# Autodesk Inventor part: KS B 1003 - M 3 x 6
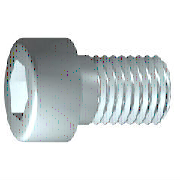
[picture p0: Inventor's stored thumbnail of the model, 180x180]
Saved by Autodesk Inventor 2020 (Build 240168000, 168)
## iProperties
Created: 2019-01
Part Number: KS B 1003 - M 3 x 6
Material: Acier, doux
Description: Vis à tôle à tête hexagonale
Document SubType Name: Modeling
Standard: KS B 1003
Designer: bruno
Standards Organization: KS
Language: fr-FR
Size Designation: M 3 x 6
Categories: <MemberInstance><Categories><Category DisplayName="Visserie" InternalName="e4da775c-781d-43d5-af7c-5136215cf5a6" Mnemonic="FSTN"><Category DisplayName="Vis" Int
Density: 7.85 g/cm^3
Appearance: Semi-poli
IsCustomPart: 0
Author: bruno
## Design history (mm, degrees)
sketch "Esquisse1"
  geometry: L1 (-0.867, 0)-(6, 0); L2 (6, 0)-(6, 1.5); L3 (6, 1.5)-(1.25, 1.5); L4 (1.25, 1.5)-(0.943, 1.5); L5 (0.943, 1.5)-(0, 1.5); L6 (0, 1.5)-(0, 2.75); L7 (0, 2.75)-(-3, 2.75); L8 (-3, 2.75)-(-3, 1.443); L9 (-3, 1.443)-(-1.7, 1.443); L10 (-1.7, 1.443)-(-0.867, 0); L11 (-4.8, 0)-(7.8, 0) reference; L12 (0, -0.55)-(0, 3.3) reference; L13 (1.25, 1.5)-(0, 1.5)
  constraints: 22 end point, 6 parallel, 2 collinear, 2 perpendicular, 1 horizontal, 1 point on line
  dimensions: "d1" = 4.75 distance from line of L3.end L2 (= GEL); "d2" = 0.30683 distance of L4.end L3.end (computed from GAL); "d3" = 3 distance between parallel lines of L8 L6 (= KOH); "d4" = 1.3 distance of L8.end L9.end (= INTI); "d5" = 60 deg angle of L10 L1; "d6" = 3 diameter of L3 L1 (= GD); "d7" = 3 diameter of L5 L1 (= BDM); "d8" = 2.88675 diameter of L9 L1 (= 1.1547 x SW); "d9" = 5.5 diameter of L7 L1 (= KOD); "d26" = 6 distance between parallel lines of L12 L2 (= NLG)
revolve "Corps" sketch "Esquisse1" stored, may be unused: angle "d10" = 90 deg
sketch "Esquisse2"
  geometry: L1 (0, -3.85)-(0, 3.85) reference; L2 (-3.85, 0)-(3.85, 0) reference; L3 (1.443, 0)-(0.722, -1.25); L4 (0.722, -1.25)-(-0.722, -1.25); L5 (-0.722, -1.25)-(-1.443, 0); L6 (-1.443, 0)-(-0.722, 1.25); L7 (-0.722, 1.25)-(0.722, 1.25); L8 (0.722, 1.25)-(1.443, 0); 2 further points
  constraints: 12 end point, 1 coincident, 1 horizontal alignment, 1 point on line, 12 other
extrude "Rainure" join sketch "Esquisse2" stored distance "d11" = 10; taper "d12" = 0 deg
workplane "Work Plane1"
fillet "Fillet2" dims "d30" = 0.1 (= R)
body "Solid1"
fillet "Congé1" dims "d17" = 0.3 (= RR)
feature "Filetage" dims "d13" = 4.75 (= GEL), "d14" = 0
chamfer "Chanfrein1" distance "d15" = 0.30673 (= -0.5 x SPD + 0.5 x GD); stored, may be unused: second distance "d16" = 0.30673 (= GUL), angle "d27" = 45 deg
other parameters: "GD" = 3 (= NND) [user parameter; used in 2 equation terms], "NLG" = 6 [user parameter; used in 1 equation term], "GEL" = 4.75 [user parameter; used in 2 equation terms], "KOD" = 5.5 [user parameter; used in 1 equation term], "KOH" = 3 [user parameter; used in 1 equation term], "INTI" = 1.3 [user parameter; used in 1 equation term], "GAL" = 0.30673 (= 0.61345 x PTC) [user parameter; used in 1 equation term], "GUL" = 0.30673 (= 0.61345 x PTC) [user parameter; used in 1 equation term], "BDM" = 3 (= NND) [user parameter; used in 1 equation term], "SW" = 2.5 [user parameter; used in 2 equation terms], "RR" = 0.3 [user parameter; used in 1 equation term], "SPD" = 2.38655 (= NND - 1.2269 x PTC) [user parameter; used in 1 equation term], "d19" = 0, "d28" = 0, "d29" = 0, "R" = 0.1 [user parameter; used in 1 equation term], "PHH" = 0.1 [user parameter], "GD1" = 2.38655 (= THREADDIA - 1.2269 x PTC) [user parameter], "THREADDIA" = 3 [user parameter; used in 1 equation term], "FAWI" = 45 deg [user parameter], "PTC" = 0.5 [user parameter; used in 5 equation terms], "NND" = 3 [user parameter; used in 3 equation terms], "TOA" = 30 deg [user parameter], "E0" = 2.8875 (= 1.155 x SW) [user parameter]
